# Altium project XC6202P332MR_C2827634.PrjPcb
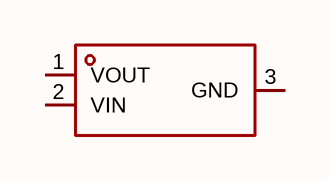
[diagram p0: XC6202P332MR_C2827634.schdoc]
1 sheet, 1 parts. Net scope: global (net labels, ports and power ports of the same name join across sheets).

## Sheet XC6202P332MR_C2827634.schdoc
size 127 x 101 mm

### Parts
U?  xc6202p332mr  [SOT-23-3_L2.9-W1.6-P1.90-LS2.8-BR]  (value not drawn)

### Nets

Not connected (* = marked no-connect by the designer): U? 1(VOUT) 2(VIN) 3(GND)

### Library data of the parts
U? = xc6202p332mr: 输出极性:正极;工作电压:15V;输出电压:3.3V;输出电流:150mA;电源纹波抑制比(PSRR):40dB@(1kHz);输出类型:固定;; Manufacturer: TECH PUBLIC(台舟); Symbol: XC6202P332MR_C2827634; AddInBom: yes; ModelId: 89cb27a44ab2466697082bb9fd73a7d0; ModelName: SOT-23-3L_L2.9-W1.6-H1.1-LS2.8-P0.95; ModelTransform: 114.173,110.236,0,90,0,0,0,0,0; Output Configuration: 正极; Voltage - Supply: 15V; Output Voltage: 3.3V; Output Current: 150mA; Voltage Dropout: 160mV@(100mA); standby current: 2uA; Output Type: 固定; Number of Outputs: 1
